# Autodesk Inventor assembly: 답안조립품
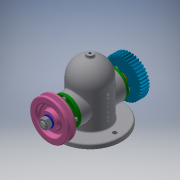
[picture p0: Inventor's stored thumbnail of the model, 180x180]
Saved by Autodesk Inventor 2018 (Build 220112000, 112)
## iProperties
Created: 2019-11
Part Number: 답안조립품
Material: 일반
Document SubType Name: Assembly
Designer: USER
Author: USER
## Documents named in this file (14)
- C:\Users\USER\Desktop\491104V1050\답안조립품.iam
- C:\Users\USER\Desktop\491104V1050\본체.ipt
- C:\Users\USER\Desktop\491104V1050\V-벨트풀리.ipt
- V-벨트풀리.ipt
- C:\Users\USER\Desktop\491104V1050\너트 M12x1.25.ipt
- C:\Users\USER\Desktop\491104V1050\베어링 6203.ipt
- C:\Users\USER\Desktop\491104V1050\볼트 M4.ipt
- C:\Users\USER\Desktop\491104V1050\부시.ipt
- C:\Users\USER\Desktop\491104V1050\스퍼기어.ipt
- C:\Users\USER\Desktop\491104V1050\오일 실 26 38 8.ipt
- C:\Users\USER\Desktop\491104V1050\와셔 12x24.ipt
- C:\Users\USER\Desktop\491104V1050\축.ipt
- C:\Users\USER\Desktop\491104V1050\커버.ipt
- C:\Users\USER\Desktop\491104V1050\키 5x5x12.ipt
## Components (1 placed, 1 different names)
1. V-벨트풀리:1
